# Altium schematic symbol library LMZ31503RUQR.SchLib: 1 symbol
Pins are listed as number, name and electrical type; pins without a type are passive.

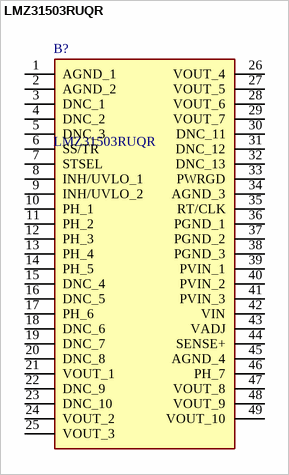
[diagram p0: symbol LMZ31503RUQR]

## LMZ31503RUQR
designator B?
Non-Isolated DC/DC Converters 3A Power Module w/ 4.5V-14.5V Input; Manufacturer_Name: Texas Instruments; Geometry.Height: 2mm
footprint LMZ31503RUQR
pins: 1 AGND_1, 2 AGND_2, 3 DNC_1, 4 DNC_2, 5 DNC_3, 6 SS/TR, 7 STSEL, 8 INH/UVLO_1, 9 INH/UVLO_2, 10 PH_1, 11 PH_2, 12 PH_3, 13 PH_4, 14 PH_5, 15 DNC_4, 16 DNC_5, 17 PH_6, 18 DNC_6, 19 DNC_7, 20 DNC_8, 21 VOUT_1, 22 DNC_9, 23 DNC_10, 24 VOUT_2, 25 VOUT_3, 26 VOUT_4, 27 VOUT_5, 28 VOUT_6, 29 VOUT_7, 30 DNC_11, 31 DNC_12, 32 DNC_13, 33 PWRGD, 34 AGND_3, 35 RT/CLK, 36 PGND_1, 37 PGND_2, 38 PGND_3, 39 PVIN_1, 40 PVIN_2, 41 PVIN_3, 42 VIN, 43 VADJ, 44 SENSE+, 45 AGND_4, 46 PH_7, 47 VOUT_8, 48 VOUT_9, 49 VOUT_10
